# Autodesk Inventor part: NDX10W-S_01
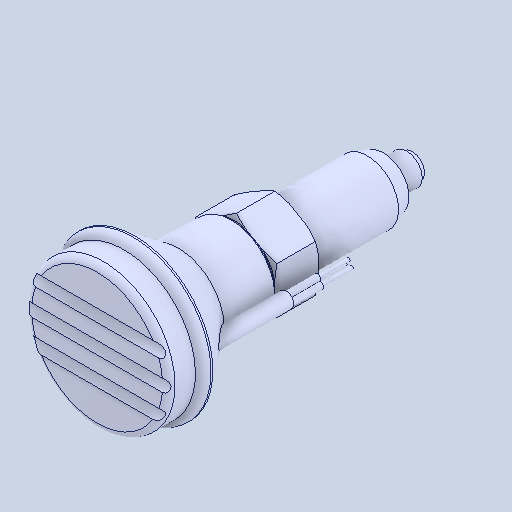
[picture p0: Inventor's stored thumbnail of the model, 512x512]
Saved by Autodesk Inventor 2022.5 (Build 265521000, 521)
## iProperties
Created: 2024-05
Part Number: NDX10W-S_01
Material: 一般
Document SubType Name: Modeling
Designer: ImaoCorp
Density: 1 g/cm^3
Appearance: 既定
Author: ImaoCorp
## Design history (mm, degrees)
feature "NDX10W-S_01"
node "ソリッド1"
